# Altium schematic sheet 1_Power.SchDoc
size A4; SheetNumber: 5; SheetTotal: 5
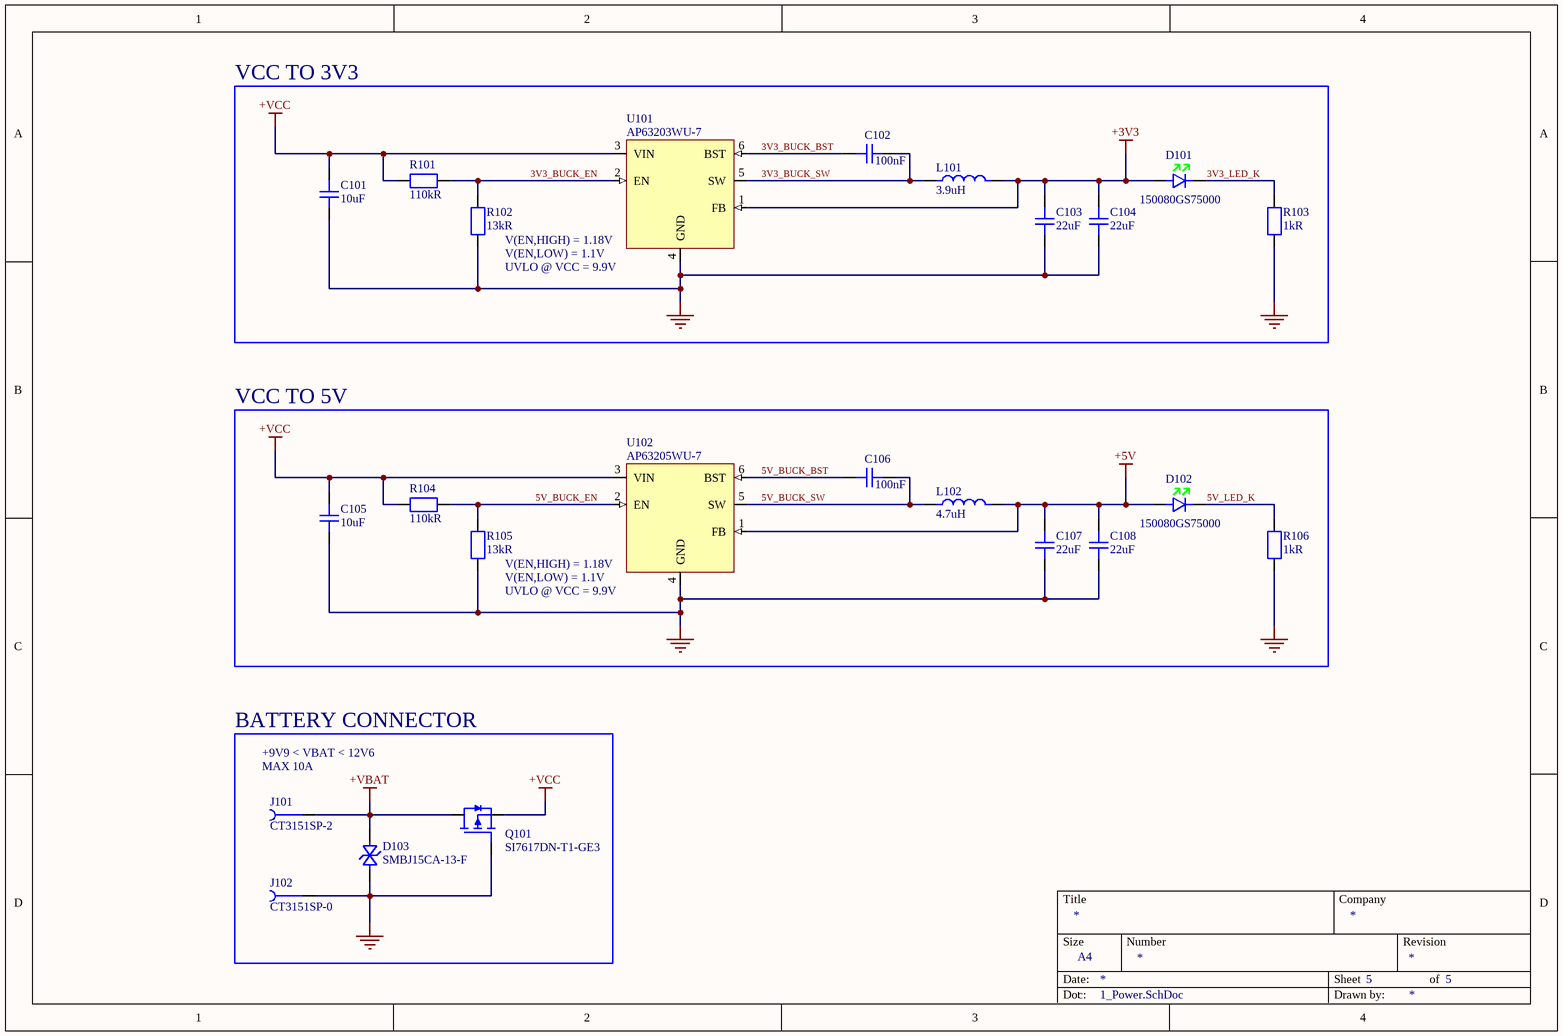
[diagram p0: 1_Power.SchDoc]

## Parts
C101  value 10uF  [C_Yageo_CC_0805_A]  (hidden comment: CC0805KRX5R7BB106)
C102  value 100nF  [C_Yageo_CC_0402_A]  (hidden comment: CC0402MRX5R6BB104)
C103  value 22uF  [C_Yageo_CC_0805_A]  (hidden comment: CC0805MKX5R6BB226)
C104  value 22uF  [C_Yageo_CC_0805_A]  (hidden comment: CC0805MKX5R6BB226)
C105  value 10uF  [C_Yageo_CC_0805_A]  (hidden comment: CC0805KRX5R7BB106)
C106  value 100nF  [C_Yageo_CC_0402_A]  (hidden comment: CC0402MRX5R6BB104)
C107  value 22uF  [C_Yageo_CC_0805_A]  (hidden comment: CC0805MKX5R6BB226)
C108  value 22uF  [C_Yageo_CC_0805_A]  (hidden comment: CC0805MKX5R6BB226)
D101  150080GS75000  [D_LED_We_150080GS75000]
D102  150080GS75000  [D_LED_We_150080GS75000]
D103  SMBJ15CA-13-F  [D_TVS_BI_Diodes_SMBJ15CA-13-F_A]
J101  CT3151SP-2  [J_CalTest_CT3151SP-2]
J102  CT3151SP-0  [J_CalTest_CT3151SP-0]
L101  value 3.9uH  [L_Murata_1255AY-XXXX=P3]  (hidden comment: 1255AY-3R9N=P3)
L102  value 4.7uH  [L_Murata_1255AY-XXXX=P3]  (hidden comment: 1255AY-4R7M=P3)
Q101  SI7617DN-T1-GE3  [Q_Vishay_PowerPACK-1212-8]
R101  value 110kR  [R_Yageo_RCL_0402_A]  (hidden comment: RC0402FR-07110KL)
R102  value 13kR  [R_Yageo_RCL_0402_A]  (hidden comment: RC0402FR-0713KL)
R103  value 1kR  [R_Yageo_RCL_0402_A]  (hidden comment: RC0402FR-071KL)
R104  value 110kR  [R_Yageo_RCL_0402_A]  (hidden comment: RC0402FR-07110KL)
R105  value 13kR  [R_Yageo_RCL_0402_A]  (hidden comment: RC0402FR-0713KL)
R106  value 1kR  [R_Yageo_RCL_0402_A]  (hidden comment: RC0402FR-071KL)
U101  AP63203WU-7  [U_Diodes_AP623xx]
U102  AP63205WU-7  [U_Diodes_AP623xx]

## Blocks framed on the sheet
VCC TO 3V3: C101-C104 D101 L101 R101-R103 U101
VCC TO 5V: C105-C108 D102 L102 R104-R106 U102
BATTERY CONNECTOR: D103 J101 J102 Q101

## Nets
+3V3: C103.2 C104.2 D101.1 L101.2 U101.1(FB)
+5V: C107.2 C108.2 D102.1 L102.2 U102.1(FB)
+VBAT: D103.1 J101.1 Q101.1(D)
+VCC: C101.2 C105.2 Q101.3(S) R101.2 R104.2 U101.3(VIN) U102.3(VIN)
GND: C101.1 C103.1 C104.1 C105.1 C107.1 C108.1 D103.2 J102.1 Q101.2(G) R102.1 R103.1 R105.1 R106.1 U101.4(GND) U102.4(GND)
3V3_BUCK_BST: C102.2 U101.6(BST)
3V3_BUCK_EN: R101.1 R102.2 U101.2(EN)
3V3_BUCK_SW: C102.1 L101.1 U101.5(SW)
3V3_LED_K: D101.2 R103.2
5V_BUCK_BST: C106.2 U102.6(BST)
5V_BUCK_EN: R104.1 R105.2 U102.2(EN)
5V_BUCK_SW: C106.1 L102.1 U102.5(SW)
5V_LED_K: D102.2 R106.2

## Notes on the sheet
- (near U101) V(EN,HIGH) = 1.18V
- V(EN,LOW) = 1.1V
- (near U101) UVLO @ VCC = 9.9V
- (near U102) V(EN,HIGH) = 1.18V
- (near U102) UVLO @ VCC = 9.9V
- +9V9 < VBAT < 12V6
- (near J101) MAX 10A

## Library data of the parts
C101 C105 = CMP-001-00018-3: 0805 10 uF 16 V ±10% Tolerance X5R Multilayer Ceramic Chip Capacitor; Voltage Rating (DC): 16V
C102 C106 = CMP-001-00009-9: Multilayer Ceramic Capacitor, 0.1 uF, 10 V, ± 20%, X7R, 0402 [1005 Metric]; Dielectric: X5R; Temperature Coefficient: 30ppm/°C; Voltage Rating: 10V
C103 C104 C107 C108 = CMP-001-00014-5: Multilayer Ceramic Capacitor, 22 uF, 10 V, ± 20%, X5R, 0805 [2012 Metric]; Voltage Rating (DC): 10V
D101 D102 = CMP-007-00000-6: WURTH ELEKTRONIK - 150080GS75000 - LED, Green, SMD, 0805, 30 mA, 3.2 V, 520 nm; Forward Current: 30mA; Forward Voltage: 3.2V; Luminous Intensity: 450mcd; Max Reverse Voltage (DC): 5V; Lens Transparency: Clear; Power Dissipation: 105mW; Lens Style: Clear,Flat,Rectangular; Lens Size: 1.25mm; Viewing Angle: 140°; Test Current: 20mA; Dominant Wavelength: 520nm; Lens Color: Colorless
D103 = CMP-004-00000-8: Tvs Diode, Bidir, 15V, 600W, Do-214Aa Rohs Compliant: Yes; Max Reverse Leakage Current: 5uA; Reverse Breakdown Voltage: 16.7V; Breakdown Voltage: 19.2V; Clamping Voltage: 24.4V; Power Line Protection: No; Max Surge Current: 24A; Number of Bidirectional Channels: 1; Test Current: 1mA; Value: 280pF; Polarity: Bidirectional; Diode Type: ZENER
J101 = CMP-002-00001-9: Conn 4mm Safety Banana Jack F 1 POS Solder RA Thru-Hole 1 Port Bag; pin to pad: 1>1+2+3+4; Body Material: Nylon,Polyamide,PA66; Insulation: Mating End Insulated; Gender: Female
J102 = CMP-002-00000-11: Conn 4mm Safety Banana Jack F 1 POS Solder RA Thru-Hole 1 Port Bag; pin to pad: 1>1+2+3+4; Body Material: Nylon,Polyamide,PA66; Insulation: Mating End Insulated; Gender: Female
L101 = CMP-006-00002-2: Inductor Power Shielded Wirewound 3.9uH 30% 100KHz Ferrite 4.2A 0.0264Ohm DCR 2424 T/R; DC Resistance (DCR): 26.4mR; Saturation Current: 4.7A
L102 = CMP-006-00001-5: Inductor Power Shielded Wirewound 4.7uH 20% 100KHz Ferrite 4A 0.0276Ohm DCR 2424 T/R; DC Resistance (DCR): 27.6mR; Current Rating: 4.5A
Q101 = CMP-00000-9: P CHANNEL MOSFET, -30V, 35A; Transistor; Transistor Polarity: P Channel; Continuous Drain Current Id: -35A; Source; pin to pad: 1>5 2>4 3>1+2+3; Rise Time: 43ns; Drain to Source Resistance: 12.3mR; Turn-Off Delay Time: 30ns; Turn-On Delay Time: 40ns; Threshold Voltage: -2.5V; Max Power Dissipation: 52W; Fall Time: 11ns; Power Dissipation: 3.7W; Polarity: P-CHANNEL; Number of Elements: 1; Input Capacitance: 1.8nF; Gate to Source Voltage (Vgs): 25V
R101 R104 = CMP-009-00000-7: SMD Chip Resistor, 110 kOhm, ± 1%, 63 mW, 0402 [1005 Metric], Thick Film, General Purpose; Max Power Dissipation: 63mW; Voltage Rating (DC): 50V; Temperature Coefficient: 100ppm/°C
R102 R105 = CMP-009-00001-7: SMD Chip Resistor, 13 kOhm, ± 1%, 63 mW, 0402 [1005 Metric], Thick Film, General Purpose; Temperature Coefficient: 100ppm/°C; Voltage Rating: 50V; Max Power Dissipation: 63mW; Power Rating: 62.5mW
R103 R106 = CMP-009-00002-7: SMD Chip Resistor, 1 kOhm, ± 1%, 62.5 mW, 0402 [1005 Metric], Thick Film, General Purpose; Temperature Coefficient: 100ppm/°C; Voltage Rating (AC): 50V; Power Rating: 62.5mW; Max Power Dissipation: 63mW
U101 = CMP-019-00004-9: AP63203 Series 3.3 V 2 A SMT Fixed Low IQ Synchronous Buck - TSOT-26; Max Duty Cycle: 100%; Output Voltage: 3.3V; Number of Outputs: 1; Max Supply Voltage: 32V; Switching Frequency: 1.1MHz; Min Supply Voltage: 3.8V; Nominal Supply Current: 22uA; Output Current: 2A
U102 = CMP-019-00003-9: AP63205 Series 32 V 2 A 1.1 MHz Synchronous Buck Converter -TSOT-26; Number of Outputs: 1; Max Duty Cycle: 100%; Output Current: 2A; Switching Frequency: 1.1MHz; Max Supply Voltage: 32V; Output Voltage: 5V; Nominal Supply Current: 22uA; Min Supply Voltage: 3.8V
